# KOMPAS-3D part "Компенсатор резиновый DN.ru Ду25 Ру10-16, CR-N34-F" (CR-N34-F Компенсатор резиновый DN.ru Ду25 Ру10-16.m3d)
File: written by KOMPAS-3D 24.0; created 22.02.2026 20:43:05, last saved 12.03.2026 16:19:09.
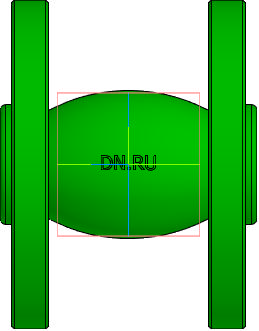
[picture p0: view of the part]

Document properties: Автор: DN.RU; Полное имя файла: CR-N34-F Компенсатор резиновый DN.ru Ду25 Ру10-16.cdw

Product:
- Body: Твердое тело2  | qty 1
    Масса: 2.463282
- Part/product: Компенсатор резиновый DN.ru Ду25 Ру10-16  | designation CR-N34-F
    Масса: 2
    Раздел спецификации: Прочие изделия
    Форматы листов документа: A3
    Комментарий: D140-02086
    Примечание: D140-02086
    additional columns: Типовые

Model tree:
1. Твердое тело2  (labels: Твердое тело2)

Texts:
  CR-N34-F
